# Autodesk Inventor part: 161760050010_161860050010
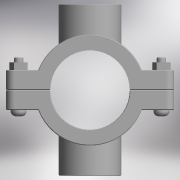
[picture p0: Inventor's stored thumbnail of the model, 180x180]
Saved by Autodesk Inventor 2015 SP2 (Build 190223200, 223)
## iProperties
Created: 2017-05
Part Number: 161760050010_161860050010
Material: Generic
Description: PLASSON DOUBLE SADDLE 50-1"
Document SubType Name: Modeling
Designer: KIM
Density: 1 g/cm^3
Appearance: Default
Author: KIM
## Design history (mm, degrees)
derived "16176.ipt"
feature "Solid1::16176.ipt"
feature "Solid2::16176.ipt"
tag "TaggingFeature1"
body "Solid1"
body "Solid2"
other parameters: "d1" = 106, "d2" = 25, "d4" = 73, "d5" = 0, "d6" = 5.3, "d7" = 106, "d8" = 0.1, "d10" = 0, "d11" = 0.5, "d20" = 0.5, "d23" = 0.5, "d37" = 8, "d38" = 33, "d39" = 0, "d40" = 3, "d41" = 5, "d42" = 0, "d43" = 6, "d44" = 3, "d45" = 0, "d46" = 0.5, "d52" = 30.291, "d53" = 21, "d54" = 0, "d55" = 25, "d57" = 0, "d58" = 54, "d60" = 0, "d63" = 36.5, "d66" = 0, "d67" = 108, "d68" = 39.3783, "d69" = 30.291, "d70" = 21, "d71" = 0, "d72" = 25, "d74" = 0, "d75" = 0.5, "B_" = 25, "G_" = 30.291, "A_" = 54, "L_" = 106, "L_1" = 73, "l_2" = 21
